// Mitsubishi GX Works2 project: 6.顺序启动   PLC: FX3U/FX3UC

PROGRAM MAIN
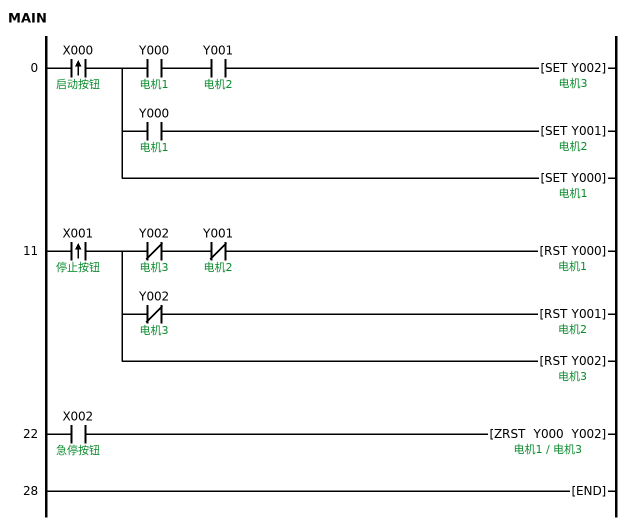
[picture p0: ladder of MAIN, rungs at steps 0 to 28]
0     LDP     X000  ; 启动按钮
      MPS
      AND     Y000  ; 电机1
      AND     Y001  ; 电机2
      SET     Y002  ; 电机3
      MRD
      AND     Y000  ; 电机1
      SET     Y001  ; 电机2
      MPP
      SET     Y000  ; 电机1
11    LDP     X001  ; 停止按钮
      MPS
      ANI     Y002  ; 电机3
      ANI     Y001  ; 电机2
      RST     Y000  ; 电机1
      MRD
      ANI     Y002  ; 电机3
      RST     Y001  ; 电机2
      MPP
      RST     Y002  ; 电机3
22    LD      X002  ; 急停按钮
      ZRST    Y000 Y002
28    END
END_PROGRAM
